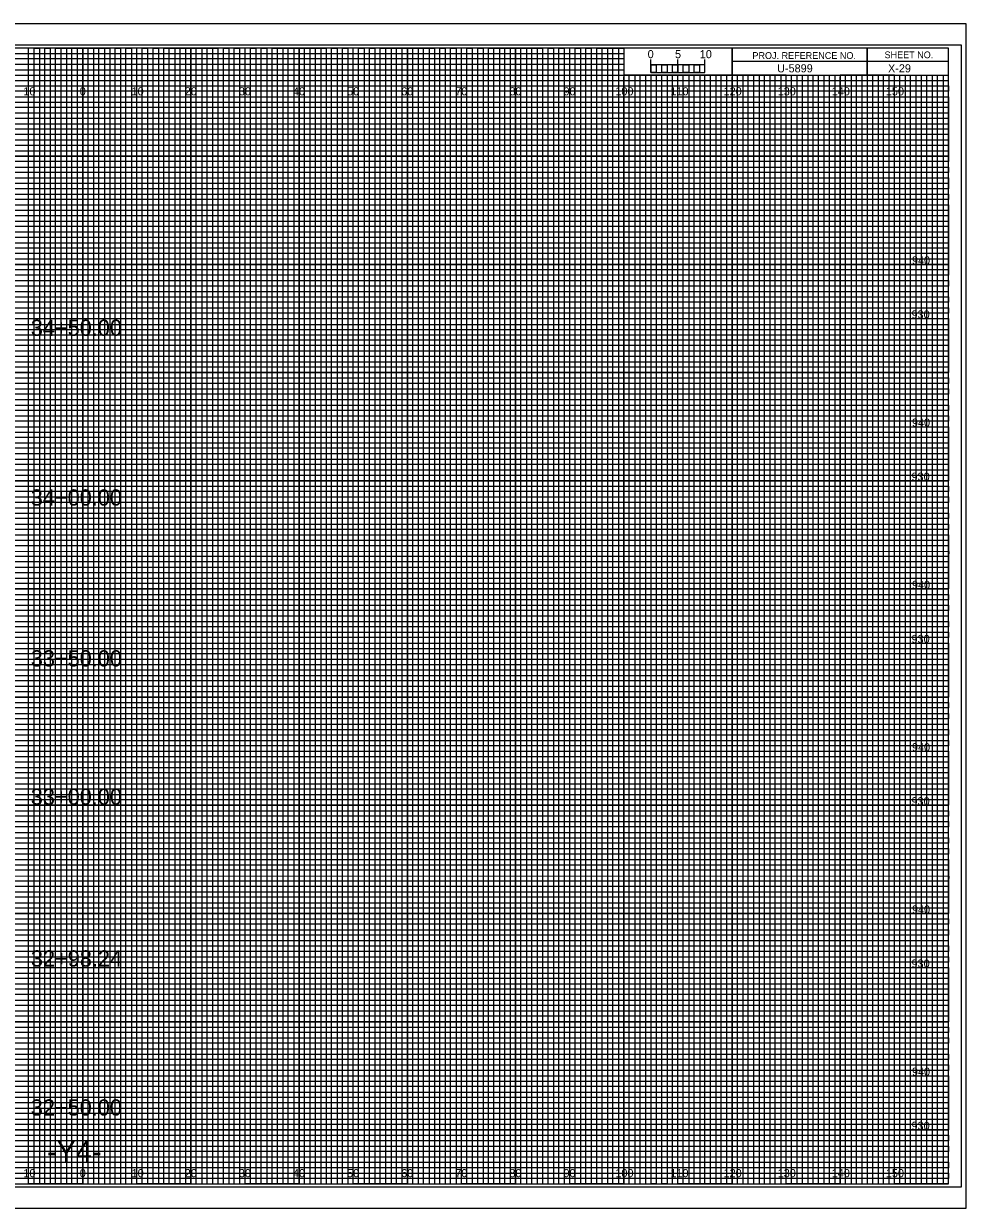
# Model space of a CAD drawing. Extents: x -13 to 323, y -4 to 214.
# Drawn here: x 149.1 to 323.3, y -4.5 to 214.5 of the extents above; entities that cross this region are included whole.
import ezdxf

# ---------------------------------------------------------------- set-up
doc = ezdxf.new("R2010")
doc.units = 0
for name, color, linetype in [('Prop XS Alignment Label', 7, 'Continuous'), ('Prop XS Bar Scale Labels', 7, 'Continuous'), ('Prop XS Elevation Labels', 7, 'Continuous'), ('Prop XS Project Number', 7, 'Continuous'), ('Prop XS Shear Point Label', 7, 'Continuous'), ('Prop XS Sheet Number', 7, 'Continuous'), ('Prop XS Station Labels', 7, 'Continuous'), ('Sheet Cross Section CELL', 7, 'Continuous'), ('Sheet Cross Section Grid Major CELL', 7, 'Continuous'), ('Sheet Cross Section Grid Middle CELL', 7, 'Continuous'), ('Sheet Cross Section Grid Minor 1 CELL', 7, 'Continuous'), ('Sheet Cross Section Grid Minor 2 CELL', 7, 'Continuous'), ('Sheet Cross Section Scale CELL', 7, 'Continuous'), ('Sheet Cutting Line CELL', 7, 'Continuous'), ('Sheet DOT Grid CELL', 7, 'Continuous'), ('Sheet Plot Border Inside CELL', 7, 'Continuous'), ('Sheet Plot Border Outside CELL', 7, 'Continuous')]:
    doc.layers.add(name, color=color, linetype=linetype)

msp = doc.modelspace()

# ---------------------------------------------------------------- linework, layer by layer
at = {"layer": 'Sheet Cross Section CELL'}
for p, q in [((305, 210), (305, 205)), ((305, 205), (305, 210)), ((280, 207.5), (280, 205)), ((320, 207.49), (280, 207.49)), ((280, 205), (320, 205))]:
    msp.add_line(p, q, dxfattribs=at)
for points in [[(320, 210), (0, 210), (0, 0), (320, 0)], [(280, 210), (260, 210), (260, 205.03), (280, 205.03)], [(320, 210), (280, 210), (280, 205), (320, 205)]]:
    msp.add_lwpolyline(points, close=True, dxfattribs=at)
at = {"layer": 'Sheet Cross Section Grid Major CELL'}
for p, q in [((150, 210), (140, 210)), ((150, 0), (150, 210)), ((170, 210), (160, 210)), ((160, 210), (160, 0)), ((170, 0), (170, 210)), ((190, 210), (180, 210)), ((180, 210), (180, 0)), ((190, 0), (190, 210)), ((210, 210), (200, 210)), ((200, 210), (200, 0)), ((210, 0), (210, 210)), ((230, 210), (220, 210)), ((220, 210), (220, 0)), ((230, 0), (230, 210)), ((250, 210), (240, 210)), ((240, 210), (240, 0)), ((250, 0), (250, 210)), ((260, 210), (260, 0)), ((270, 0), (270, 205)), ((290, 205), (280, 205)), ((280, 205), (280, 0)), ((290, 0), (290, 205)), ((310, 205), (300, 205)), ((300, 205), (300, 0)), ((310, 0), (310, 205)), ((160, 0), (150, 0)), ((180, 0), (170, 0)), ((200, 0), (190, 0)), ((220, 0), (210, 0)), ((240, 0), (230, 0)), ((260, 0), (250, 0)), ((280, 0), (270, 0)), ((300, 0), (290, 0)), ((320, 0), (310, 0)), ((320, 0), (320, 0))]:
    msp.add_line(p, q, dxfattribs=at)
for points in [[(0, 200), (320, 200), (320, 190), (0, 190)], [(0, 180), (320, 180), (320, 170), (0, 170)], [(0, 160), (320, 160), (320, 150), (0, 150)], [(0, 140), (320, 140), (320, 130), (0, 130)], [(0, 120), (320, 120), (320, 110), (0, 110)], [(0, 100), (320, 100), (320, 90), (0, 90)], [(0, 80), (320, 80), (320, 70), (0, 70)], [(0, 60), (320, 60), (320, 50), (0, 50)], [(0, 40), (320, 40), (320, 30), (0, 30)], [(0, 20), (320, 20), (320, 10), (0, 10)]]:
    msp.add_lwpolyline(points, dxfattribs=at)
at = {"layer": 'Sheet Cross Section Grid Middle CELL'}
for points in [[(145, 0), (155, 0), (155, 210), (165, 210), (165, 0), (175, 0), (175, 210), (185, 210), (185, 0), (195, 0), (195, 210), (205, 210), (205, 0), (215, 0), (215, 210), (225, 210), (225, 0), (235, 0), (235, 210), (245, 210), (245, 0), (255, 0), (255, 210), (259.93, 210), (260, 210), (260, 205), (264.99, 205), (264.99, 0), (275, 0), (275, 205), (285, 205), (285, 0), (295, 0), (295, 205), (305, 205), (305, 0), (315, 0), (315, 205)], [(0, 205), (275, 205)], [(0, 185), (320, 185), (320, 195), (0, 195)], [(0, 165), (320, 165), (320, 175), (0, 175)], [(0, 145), (320, 145), (320, 155), (0, 155)], [(0, 125), (320, 125), (320, 135), (0, 135)], [(0, 105), (320, 105), (320, 115), (0, 115)], [(0, 85), (320, 85), (320, 95), (0, 95)], [(0, 65), (320, 65), (320, 75), (0, 75)], [(0, 45), (320, 45), (320, 55), (0, 55)], [(0, 25), (320, 25), (320, 35), (0, 35)], [(0, 5), (320, 5), (320, 15), (0, 15)]]:
    msp.add_lwpolyline(points, dxfattribs=at)
at = {"layer": 'Sheet Cross Section Grid Minor 1 CELL'}
for p, q in [((0, 209), (260, 209)), ((260, 209), (260, 207.98)), ((260, 207.98), (0, 207.98)), ((0, 207), (260, 207)), ((260, 205.89), (0, 205.89)), ((260, 207), (260, 205.89)), ((0, 204), (320, 204))]:
    msp.add_line(p, q, dxfattribs=at)
for points in [[(0, 203), (270, 203), (320, 203), (320, 202), (0, 202)], [(0, 201), (320, 201), (320, 199), (0, 199)], [(0, 198), (320, 198), (320, 197), (0, 196.98)], [(0, 196), (320, 196), (320, 194), (0, 194)], [(0, 193), (320, 193), (320, 192), (0, 192)], [(0, 191), (320, 191), (320, 189), (0, 189)], [(0, 188), (320, 188), (320, 187), (0, 187)], [(0, 186), (320, 186), (320, 184), (0, 184)], [(0, 183), (320, 183), (320, 182), (0, 182)], [(0, 181), (320, 181), (320, 179), (0, 179)], [(0, 178), (320, 178), (320, 177), (0, 177)], [(0, 176), (320, 176), (320, 173.95), (320, 173), (320, 172), (0, 172)], [(0, 174), (320, 174), (320, 173), (0, 173)], [(0, 171), (320, 171), (320, 169), (0, 169.03)], [(0, 169.03), (320, 169), (320, 168), (0, 168)], [(0, 167), (320, 167), (320, 166), (0, 166)], [(0, 164), (320, 164), (320, 163), (0, 163)], [(0, 162), (320, 162), (320, 161), (0, 161)], [(-0.07, 158.89), (320, 158.89), (320, 157.88), (-0.07, 157.88)], [(0, 157), (320, 157), (320, 156), (0, 156)], [(0, 154), (320, 154), (320, 153), (0, 153)], [(0, 152), (320, 152), (320, 151), (0, 151)], [(0, 149), (320, 149), (320, 148), (0, 148)], [(0, 147), (320, 147), (320, 146), (0, 146)], [(0, 144), (320, 144), (320, 143), (0, 143)], [(0, 142), (320, 142), (320, 141), (0, 141)], [(0, 139), (320, 139), (319.99, 137.98), (0, 138)], [(0, 137), (320, 137), (320, 136), (0, 136)], [(0, 134), (320, 134), (320, 133), (0, 133)], [(0, 132), (320, 132), (320, 131), (0, 131)], [(0, 129), (320, 129), (320, 128), (0, 128)], [(0, 127), (320, 127), (320, 126), (0, 126)], [(0, 124), (320, 124), (320, 123), (0, 123)], [(0, 122), (320, 122), (320, 121), (0, 121)], [(0, 119), (320, 119), (320, 118), (0, 118)], [(0, 116.99), (320.07, 116.91), (320, 116), (0, 116)], [(0, 114), (320, 114), (320, 113), (0, 113)], [(0, 112), (320, 112), (320, 111), (0, 111)], [(0, 109), (320, 109), (320, 108), (0, 108)], [(0, 107), (320, 107), (320, 106), (0, 106)], [(0, 104), (320, 104), (320, 103), (0, 103)], [(0, 102), (320, 102), (320, 101), (0, 101)], [(0, 99), (320, 99), (320, 98), (0, 98)], [(0, 97), (320, 97), (320, 96), (0, 96)], [(0, 94), (320, 94), (320, 93), (0, 93)], [(0, 92), (320, 92), (320, 91), (0, 91)], [(0, 89), (320, 89), (320, 88), (0, 88)], [(0, 87), (320, 87), (320, 86), (0, 86)], [(0, 84), (320, 84), (320, 83), (0, 83)], [(0, 82), (320, 82), (320, 81), (0, 81)], [(0, 79), (320, 79), (319.99, 77.98), (0, 78)], [(0, 77), (320, 77), (320, 76), (0, 76)], [(0, 74), (320, 74), (320, 73), (0, 73)], [(0, 72), (320, 72), (320, 71), (0, 71)], [(0, 69), (320, 69), (320, 68), (0, 68)], [(0, 67), (320, 67), (320, 66), (0, 66)], [(0, 64), (320, 64), (320, 63), (0, 63)], [(0, 62), (320, 62), (320, 61), (0, 61)], [(0, 59), (320, 59), (320, 58), (0, 58)], [(0, 56.99), (320.07, 56.91), (320, 56), (0, 56)], [(0, 54), (320, 54), (320, 53), (0, 53)], [(0, 52), (320, 52), (320, 51), (0, 51)], [(0, 49), (320, 49), (320, 48), (0, 48)], [(0, 47), (320, 47), (320, 46), (0, 46)], [(0, 44), (320, 44), (320, 43), (0, 43)], [(0, 42), (320, 42), (320, 41), (0, 41)], [(0, 39), (320, 39), (320, 38), (0, 38)], [(0, 37), (320, 37), (320, 36), (0, 36)], [(0, 34), (320, 34), (320, 33), (0, 33)], [(0, 32), (320, 32), (320, 31), (0, 31)], [(0, 29), (320, 29), (320, 28), (0, 28)], [(0, 27), (320, 27), (320, 26), (0, 26)], [(0, 24), (320, 24), (320, 23), (0, 23)], [(0, 22), (320, 22), (320, 21), (0, 21)], [(0, 19), (320, 19), (320, 18), (0, 18)], [(0, 17), (320, 17), (320, 16), (0, 16)], [(0, 14), (320, 14), (320, 13), (0, 13)], [(0, 12), (320, 12), (320, 11), (0, 11)], [(0, 9), (320, 9), (320, 8), (0, 8)], [(0, 7), (320, 7), (320, 6), (0, 6)], [(0, 4), (320, 4), (320, 3), (0, 3)], [(0, 2), (320, 2), (320, 1), (0, 1)]]:
    msp.add_lwpolyline(points, dxfattribs=at)
at = {"layer": 'Sheet Cross Section Grid Minor 2 CELL'}
for p, q in [((267, 205), (266.01, 205)), ((266.01, 205), (266.01, 0)), ((267, 0), (267, 205)), ((269, 205), (268, 205)), ((268, 205), (268, 0)), ((269, 0), (269, 205)), ((266.01, 0), (265, 0)), ((268, 0), (267, 0))]:
    msp.add_line(p, q, dxfattribs=at)
for points in [[(150, 0), (151, 0), (151, 210), (152, 210), (152, 0)], [(152, 0), (153, 0), (153, 210), (154, 210), (154, 0)], [(155, 0), (156, 0), (156, 210), (157, 210), (157, 0)], [(157, 0), (158, 0), (158, 210), (159, 210), (159, 0)], [(160, 0), (161, 0), (161, 210), (162, 210), (162, 0)], [(162, 0), (163, 0), (163, 210), (164, 210), (164, 0)], [(165, 0), (166, 0), (166, 210), (167, 210), (167, 0)], [(167, 0), (168, 0), (168, 210), (169, 210), (169, 0)], [(170, 0), (171, 0), (171, 210), (172, 210), (172, 0)], [(172, 0), (173, 0), (173, 210), (174, 210), (174, 0)], [(175, 0), (176, 0), (176, 210), (177, 210), (177, 0)], [(177, 0), (178, 0), (178, 210), (179, 210), (179, 0)], [(180, 0), (181, 0), (181, 210), (182, 210), (182, 0)], [(182, 0), (183, 0), (183, 210), (184, 210), (184, 0)], [(185, 0), (186, 0), (186, 210), (187, 210), (187, 0)], [(187, 0), (188, 0), (188, 210), (189, 210), (189, 0)], [(190, 0), (191, 0), (191, 210), (192, 210), (192, 0)], [(192, 0), (193, 0), (193, 210), (194, 210), (194, 0)], [(195, 0), (196, 0), (196, 210), (197, 210), (197, 0)], [(197, 0), (198, 0), (198, 210), (199, 210), (199, 0)], [(200, 0), (201, 0), (201, 210), (202, 210), (202, 0)], [(202, 0), (203, 0), (203, 210), (204, 210), (204, 0)], [(205, 0), (206, 0), (206, 210), (207, 210), (207, 0)], [(207, 0), (208, 0), (208, 210), (209, 210), (209, 0)], [(210, 0), (211, 0), (211, 210), (212, 210), (212, 0)], [(212, 0), (213, 0), (213, 210), (214, 210), (214, 0)], [(215, 0), (216, 0), (216, 210), (217, 210), (217, 0)], [(217, 0), (218, 0), (218, 210), (219, 210), (219, 0)], [(220, 0), (221, 0), (221, 210), (222, 210), (222, 0)], [(222, 0), (223, 0), (223, 210), (224, 210), (224, 0)], [(225, 0), (226, 0), (226, 210), (227, 210), (227, 0)], [(227, 0), (228, 0), (228, 210), (229, 210), (229, 0)], [(230, 0), (231, 0), (231, 210), (232, 210), (232, 0)], [(232, 0), (233, 0), (233, 210), (234, 210), (234, 0)], [(235, 0), (236, 0), (236, 210), (237, 210), (237, 0)], [(237, 0), (238, 0), (238, 210), (239, 210), (239, 0)], [(240, 0), (241, 0), (241, 210), (242, 210), (242, 0)], [(242, 0), (243, 0), (243, 210), (244, 210), (244, 0)], [(245, 0), (246, 0), (246, 210), (247, 210), (247, 0)], [(247, 0), (248, 0), (248, 210), (249, 210), (249, 0)], [(250, 0), (251, 0), (251, 210), (252, 210), (252, 0)], [(252, 0), (253, 0), (253, 210), (254, 210), (254, 0)], [(255, 0), (256, 0), (256, 210), (257, 210), (257, 0)], [(257, 0), (258, 0), (258, 210), (259, 210), (259, 0)], [(260, 0), (261, 0), (261, 205), (262.02, 205), (262.02, 0)], [(262, 0), (263, 0), (263, 205), (263.99, 205), (263.99, 0)], [(270, 0), (270.98, 0), (270.98, 205), (272, 205), (272, 0)], [(272, 0), (273, 0), (273, 205), (274.05, 205), (274.05, 0)], [(275, 0), (276, 0), (276, 205), (277, 205), (277, 0)], [(277, 0), (278, 0), (278, 205), (279, 205), (279, 0)], [(280, 0), (281, 0), (281, 205), (282, 205), (282, 0)], [(282, 0), (283, 0), (283, 205), (284, 205), (284, 0)], [(285, 0), (286, 0), (286, 205), (287, 205), (287, 0)], [(287, 0), (288, 0), (288, 205), (289, 205), (289, 0)], [(290, 0), (291, 0), (291, 205), (292, 205), (292, 0)], [(292, 0), (293, 0), (293, 205), (294, 205), (294, 0)], [(295, 0), (296, 0), (296, 205), (297, 205), (297, 0)], [(297, 0), (298, 0), (298, 205), (299, 205), (299, 0)], [(300, 0), (301, 0), (301, 205), (302, 205), (302, 0)], [(302, 0), (303, 0), (303, 205), (304, 205), (304, 0)], [(305, 0), (306, 0), (306, 205), (307, 205), (307, 0)], [(307, 0), (308, 0), (308, 205), (309, 205), (309, 0)], [(310, 0), (311, 0), (311, 205), (312, 205), (312, 0)], [(312, 0), (313, 0), (313, 205), (314, 205), (314, 0)], [(315, 0), (316, 0), (316, 205), (317, 205), (317, 0)], [(317, 0), (318, 0), (318, 205), (319, 205), (319, 0)]]:
    msp.add_lwpolyline(points, dxfattribs=at)
at = {"layer": 'Sheet Cross Section Scale CELL'}
for p, q in [((265, 205.49), (265, 207.9)), ((265, 206.9), (265, 207.9)), ((270, 205.49), (270, 207.9)), ((275, 205.49), (275, 207.9)), ((275, 206.9), (275, 207.9))]:
    msp.add_line(p, q, dxfattribs=at)
for points in [[(275, 206.9), (265, 206.9), (265, 205.49), (275, 205.49)], [(265, 206.9), (266, 206.9), (266, 205.49), (265, 205.49)], [(267, 206.9), (268, 206.9), (268, 205.49), (267, 205.49)], [(269, 206.9), (270, 206.9), (270, 205.49), (269, 205.49)], [(271, 206.9), (272, 206.9), (272, 205.49), (271, 205.49)], [(273, 206.9), (274, 206.9), (274, 205.49), (273, 205.49)]]:
    msp.add_lwpolyline(points, close=True, dxfattribs=at)
at = {"layer": 'Sheet Cutting Line CELL'}
for p, q in [((323.3, 214.5), (-13.4, 214.5)), ((-13.4, -4.5), (323.3, -4.5))]:
    msp.add_line(p, q, dxfattribs=at)
at = {"layer": 'Sheet DOT Grid CELL'}
for p, q in [((150, 0), (150, 210)), ((160, 0), (160, 210)), ((170, 0), (170, 210)), ((180, 0), (180, 210)), ((190, 0), (190, 210)), ((200, 0), (200, 210)), ((210, 0), (210, 210)), ((220, 0), (220, 210)), ((230, 0), (230, 210)), ((240, 0), (240, 210)), ((250, 0), (250, 210)), ((260, 0), (260, 204.69)), ((270, 0), (270, 204.69)), ((280, 0), (280, 204.69)), ((290, 0), (290, 204.69)), ((300, 0), (300, 204.69)), ((310, 0), (310, 204.69)), ((0, 200), (320, 200)), ((0, 190), (320, 190)), ((0, 180), (320, 180)), ((0, 170), (320, 170)), ((0, 160), (320, 160)), ((0, 150), (320, 150)), ((0, 140), (320, 140)), ((0, 130), (320, 130)), ((0, 120), (320, 120)), ((0, 110), (320, 110)), ((0, 100), (320, 100)), ((0, 90), (320, 90)), ((0, 80), (320, 80)), ((0, 70), (320, 70)), ((0, 60), (320, 60)), ((0, 50), (320, 50)), ((0, 40), (320, 40)), ((0, 30), (320, 30)), ((0, 20), (320, 20)), ((0, 10), (320, 10))]:
    msp.add_line(p, q, dxfattribs=at)
at = {"layer": 'Sheet Plot Border Inside CELL'}
msp.add_lwpolyline([(-10.8, -0.5), (322.4, -0.5), (322.4, 210.5), (-10.8, 210.5)], close=True, dxfattribs=at)
at = {"layer": 'Sheet Plot Border Outside CELL'}
msp.add_lwpolyline([(-13.4, -4.5), (323.3, -4.5), (323.3, 214.5), (-13.4, 214.5)], close=True, dxfattribs=at)

# ---------------------------------------------------------------- texts
at = {"layer": 'Prop XS Alignment Label'}
msp.add_text('-Y4-', height=4, dxfattribs=at).set_placement((153.39, 4))
at = {"layer": 'Prop XS Bar Scale Labels'}
for s, p in [('5', (269.47, 208.12)), ('10', (274.04, 208.12))]:
    msp.add_text(s, height=1.5, dxfattribs=at).set_placement(p)
at = {"layer": 'Prop XS Elevation Labels'}
for s, p in [('940', (313.26, 170)), ('930', (313.18, 160)), ('940', (313.26, 140)), ('930', (313.18, 130)), ('940', (313.26, 110)), ('930', (313.18, 100)), ('940', (313.26, 80)), ('930', (313.18, 70)), ('940', (313.26, 50)), ('930', (313.18, 40)), ('940', (313.26, 20)), ('930', (313.18, 10))]:
    msp.add_text(s, height=1.5, dxfattribs=at).set_placement(p)
at = {"layer": 'Prop XS Project Number'}
msp.add_text('U-5899', height=1.5, dxfattribs=at).set_placement((288.34, 205.5))
at = {"layer": 'Prop XS Shear Point Label'}
for s, p in [('10', (149.04, 201.25)), ('0', (159.45, 201.25)), ('0', (159.45, 201.25)), ('10', (169.04, 201.25)), ('20', (178.86, 201.25)), ('30', (188.86, 201.25)), ('40', (198.86, 201.25)), ('50', (208.86, 201.25)), ('60', (218.86, 201.25)), ('70', (228.86, 201.25)), ('80', (238.86, 201.25)), ('90', (248.86, 201.25)), ('100', (258.44, 201.25)), ('110', (268.62, 201.25)), ('120', (278.44, 201.25)), ('130', (288.44, 201.25)), ('140', (298.44, 201.25)), ('150', (308.44, 201.25)), ('10', (149.04, 1.25)), ('0', (159.45, 1.25)), ('0', (159.45, 1.25)), ('10', (169.04, 1.25)), ('20', (178.86, 1.25)), ('30', (188.86, 1.25)), ('40', (198.86, 1.25)), ('50', (208.86, 1.25)), ('60', (218.86, 1.25)), ('70', (228.86, 1.25)), ('80', (238.86, 1.25)), ('90', (248.86, 1.25)), ('100', (258.44, 1.25)), ('110', (268.62, 1.25)), ('120', (278.44, 1.25)), ('130', (288.44, 1.25)), ('140', (298.44, 1.25)), ('150', (308.44, 1.25))]:
    msp.add_text(s, height=1.5, dxfattribs=at).set_placement(p)
at = {"layer": 'Prop XS Sheet Number'}
msp.add_text('X-29', height=1.5, dxfattribs=at).set_placement((308.83, 205.5))
at = {"layer": 'Prop XS Station Labels'}
for s, p in [('34+50.00', (150.41, 156.79)), ('34+00.00', (150.41, 125.41)), ('33+50.00', (150.41, 95.67)), ('33+00.00', (150.41, 70.1)), ('32+98.24', (150.43, 40.19)), ('32+50.00', (150.41, 12.64))]:
    msp.add_text(s, height=3, dxfattribs=at).set_placement(p)
at = {"layer": 'Sheet Cross Section CELL'}
for s, p in [('PROJ. REFERENCE NO.', (283.77, 207.99)), ('SHEET NO.', (308.19, 208.12))]:
    msp.add_text(s, height=1.25, dxfattribs=at).set_placement(p)
at = {"layer": 'Sheet Cross Section Scale CELL'}
msp.add_text('0', height=1.5, dxfattribs=at).set_placement((264.41, 208.12))

doc.saveas('drawing.dxf')
